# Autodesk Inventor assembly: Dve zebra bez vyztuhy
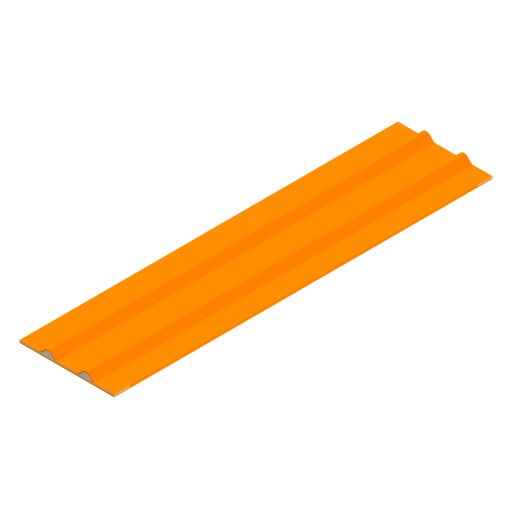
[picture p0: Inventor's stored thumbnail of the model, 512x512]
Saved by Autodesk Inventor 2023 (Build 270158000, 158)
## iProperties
Created: 2025-03
Part Number: Dve zebra bez vyztuhy
Document SubType Name: Assembly
Designer: tomik
Author: tomik
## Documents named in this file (4)
- C:\Users\tomik\Desktop\Růčka_Tomáš_přílohy\Vyztužení\Dvě žebra\Dve zebra.iam
- C:\Users\tomik\Desktop\Růčka_Tomáš_přílohy\Vyztužení\Dvě žebra\Spodni tkanina 50x200.ipt
- C:\Users\tomik\Desktop\Růčka_Tomáš_přílohy\Vyztužení\Dvě žebra\Horni tkanina.ipt
- C:\Users\tomik\Desktop\Růčka_Tomáš_přílohy\Vyztužení\Dvě žebra\Dve zebra_mustek.ipt
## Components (3 placed, 3 different names)
1. Spodni tkanina 50x200:1 — Proti sobě:1, Proti sobě:2, Stejný směr:1, Proti sobě:6, Stejný směr:5, Stejný směr:6, Proti sobě:7, Proti sobě:8, Proti sobě:9
2. Horni tkanina:1 — Proti sobě:6, Stejný směr:5, Stejný směr:6
3. Dve zebra_mustek:1 — Proti sobě:7, Proti sobě:8, Proti sobě:9
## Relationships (9: Mate 6, Flush 3)
- Proti sobě:1 [Mate]: Spodni tkanina 50x200:1
- Proti sobě:2 [Mate]: Spodni tkanina 50x200:1
- Stejný směr:1 [Flush]: Spodni tkanina 50x200:1
- Proti sobě:6 [Mate]: Spodni tkanina 50x200:1 ↔ Horni tkanina:1
- Stejný směr:5 [Flush]: Spodni tkanina 50x200:1 ↔ Horni tkanina:1
- Stejný směr:6 [Flush]: Spodni tkanina 50x200:1 ↔ Horni tkanina:1
- Proti sobě:7 [Mate]: Spodni tkanina 50x200:1 ↔ Dve zebra_mustek:1
- Proti sobě:8 [Mate]: Spodni tkanina 50x200:1 ↔ Dve zebra_mustek:1
- Proti sobě:9 [Mate]: Spodni tkanina 50x200:1 ↔ Dve zebra_mustek:1
